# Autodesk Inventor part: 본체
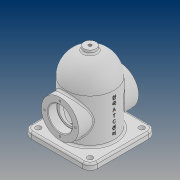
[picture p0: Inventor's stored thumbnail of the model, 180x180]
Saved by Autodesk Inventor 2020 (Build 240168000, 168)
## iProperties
Created: 2021-08
Part Number: 본체
Material: 일반
Document SubType Name: Modeling
Designer: PC312-
Density: 1 g/cm^3
Appearance: 기본값
Mass: 320.706 g
Surface Area: 800.746 cm^2
Volume: 320.706 cm^3
Author: PC312-
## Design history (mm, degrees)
sketch "스케치1"
  geometry: L1 (0, 0)-(114, 0); L2 (0, 0)-(0, -40); L3 (0, -40)-(74, -40); L4 (114, 0)-(114, 0); L5 (74, -32)-(0, -32); L6 (106, 0)-(106, 0); A1 r 40 centre (74, 0) between (74, -40) and (114, 0); A2 r 32 centre (74, 0) between (74, -32) and (106, 0); 2 further points
  constraints: 12 end point, 4 point on circle, 4 tangent, 2 centre point, 2 horizontal, 2 point on line, 2 vertical
  dimensions: "d0" = 114 distance of L1.start L1.end; "d1" = 80 diameter of L3 L1; "d35" = 8 distance between parallel lines of L3 L5; "d37" = 40 radius of A1; "d38" = 32 radius of A2
node "작업 평면1"
revolve "회전3" stored, may be unused: angle "d39" = 90 deg
sketch "스케치6"
  geometry: L1 (-55, 55)-(55, 55); L2 (55, 55)-(55, -55); L3 (55, -55)-(-55, -55); L4 (-55, -55)-(-55, 55); L5 (-55, 55)-(55, -55); L6 (55, 55)-(-55, -55); C1 r 32 at (0, 0) reference; 1 further point
  constraints: 12 end point, 2 midpoint, 2 parallel, 1 horizontal, 1 perpendicular
  dimensions: "d40" = 110 distance of L2.end L3.end; "d41" = 110 distance of L1.end L2.end
extrude "돌출2" join sketch "스케치6" distance "d42" = 10; taper "d43" = 0 deg
node "작업 평면2"
sketch "스케치7"
  geometry: L1 (55, 0)-(-55, 0) reference; L2 (55, -10)-(-55, -10) reference; C1 r 31 at (0, 38); 2 further points
  constraints: 1 centre point, 1 midpoint, 1 vertical alignment
  dimensions: "d45" = 62 diameter of C1; "d46" = 48 distance from line of L2 C1.centre
extrude "돌출3" join sketch "스케치7" stored distance "d47" = 10; taper "d48" = 0 deg
sketch "스케치8"
  geometry: C1 r 31 at (0, 0) reference; 2 further points
  constraints: 1 coincident
hole "구멍4" sketch "스케치8" at (0, 0) diameter "d49" = 40; stored, may be unused: countersink angle "d53" = 90 deg, drill point angle "d55" = 0 deg; dims "d50" = 8, "d51" = 14, "d52" = 16, "d54" = 15
sketch "스케치9"
  geometry: C1 r 31 at (0, 0) reference; 2 further points
  constraints: 1 vertical alignment
  dimensions: "d56" = 25.5 distance of point (0, 25.5) C1.centre
hole "구멍5" sketch "스케치9" at (0, 25.5) diameter "d57" = 3.242; stored, may be unused: countersink angle "d61" = 90 deg, drill point angle "d63" = 118 deg; dims "d58" = 8, "d59" = 14, "d60" = 16, "d62" = 10
sketch "스케치10"
  geometry: C1 r 20 at (0, 0) reference; 2 further points
  constraints: 1 coincident
hole "구멍6" sketch "스케치10" at (0, 0) diameter "d67" = 33; stored, may be unused: countersink angle "d71" = 90 deg, drill point angle "d73" = 118 deg; dims "d68" = 8, "d69" = 14, "d70" = 16, "d72" = 10
fillet "모깎기2" dims "d74" = 12
sketch "스케치11"
  geometry: A1 r 12 centre (43, -43) between (43, -55) and (55, -43) reference; A2 r 12 centre (-43, -43) between (-55, -43) and (-43, -55) reference; A3 r 12 centre (-43, 43) between (-43, 55) and (-55, 43) reference; A4 r 12 centre (43, 43) between (55, 43) and (43, 55) reference; 1 further point
hole "구멍7" sketch "스케치11" at (43, 43), (-43, 43), (-43, -43), (43, -43) diameter "d75" = 9; stored, may be unused: countersink angle "d79" = 90 deg, drill point angle "d81" = 118 deg; dims "d76" = 8, "d77" = 14, "d78" = 16, "d80" = 10
fillet "모깎기3" dims "d82" = 3
node "작업 평면3"
sketch "스케치12"
  geometry: C1 r 10 at (0, 0); 1 further point
  constraints: 1 centre point, 1 coincident
  dimensions: "d84" = 20 diameter of C1
extrude "돌출4" join sketch "스케치12" stored distance "d85" = 10; taper "d86" = 0 deg
sketch "스케치13"
  geometry: C1 r 10 at (0, 0) reference; 2 further points
  constraints: 1 coincident
hole "구멍8" sketch "스케치13" at (0, 0) diameter "d87" = 5.1881; stored, may be unused: countersink angle "d91" = 90 deg, drill point angle "d93" = 118 deg; dims "d88" = 12, "d89" = 14, "d90" = 16, "d92" = 16
fillet "모깎기4" dims "d94" = 3
chamfer "모따기1" distance "d95" = 1; stored, may be unused: second distance "d96" = 2, angle "d97" = 45 deg
node "작업 평면4"
sketch "스케치14"
  geometry: L1 (-10, -43)-(-10, 43) reference; 2 further points
  constraints: 1 horizontal alignment, 1 other
  dimensions: "d99" = 48 distance from line of point (38, 0) L1
feature "엠보싱1" sketch "스케치14" dims "d0" = 114, "d1" = 80, "d35" = 8, "d37" = 40, "d38" = 32, "d100" = 0.5, "d101" = 0
fillet "모깎기5" dims "d102" = 0.3
node "솔리드3"
pattern_circular "원형 패턴2" dims angle "d65" = 360 deg
mirror "미러2"
feature "A9D066F2-1C7D-4E18-AEED-F7BC21143FA4" dims "d49" = 40, "d50" = 8, "d51" = 14, "d52" = 16, "d53" = 90 deg, "d54" = 15, "d55" = 0
other parameters: "d83" = -129, "d98" = 75
